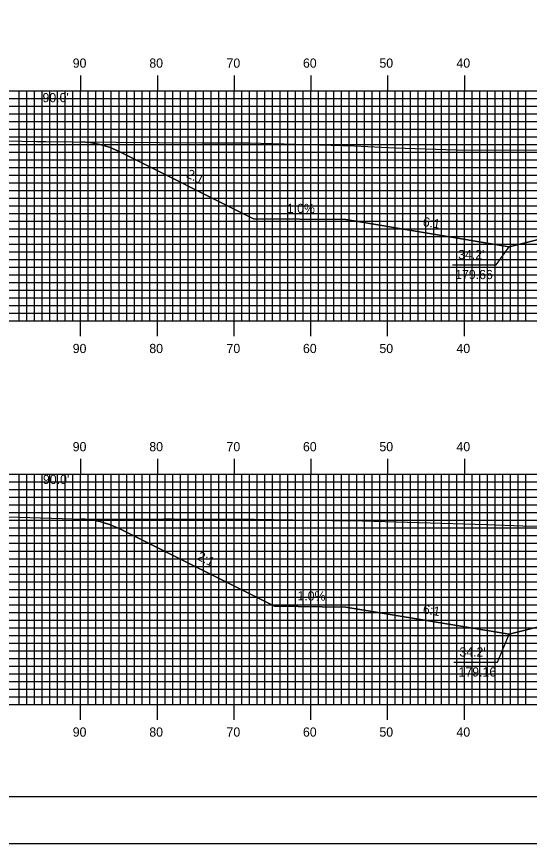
# Model space of a CAD drawing. Extents: x 1797207 to 1797550, y 442591 to 442811.
# Drawn here: x 1797274.6 to 1797341.4, y 442590.5 to 442698.3 of the extents above; entities that cross this region are included whole.
import ezdxf

# ---------------------------------------------------------------- set-up
doc = ezdxf.new("R2010")
doc.units = 0
for name, color, linetype in [('ANNOTATION', 7, 'Continuous'), ('BORDER', 7, 'Continuous'), ('D_Roadway_Centerline', 7, 'Continuous'), ('D_Roadway_SlopeLines', 7, 'Continuous'), ('D_Text_Standard', 7, 'Continuous'), ('H_V ANNOTATION', 7, 'Continuous'), ('MAJOR', 7, 'Continuous'), ('MINOR', 7, 'Continuous'), ('PLOT BOUNDARY', 7, 'Continuous'), ('S_Roadway_Centerline', 7, 'Continuous')]:
    doc.layers.add(name, color=color, linetype=linetype)

msp = doc.modelspace()

# ---------------------------------------------------------------- linework, layer by layer
at = {"layer": 'ANNOTATION'}
for points in [[(1797331.39, 442665.98), (1797337.08, 442665.98), (1797338.76, 442668.33)], [(1797331.54, 442614.18), (1797337.24, 442614.18), (1797338.76, 442617.83)]]:
    msp.add_lwpolyline(points, dxfattribs=at)
at = {"layer": 'BORDER'}
msp.add_lwpolyline([(1797223.33, 442596.67), (1797543.33, 442596.67), (1797543.33, 442806.67), (1797223.33, 442806.67)], close=True, dxfattribs=at)
at = {"layer": 'D_Roadway_Centerline'}
for points in [[(1797282.93, 442682.01), (1797284.18, 442681.93), (1797285.43, 442681.68), (1797286.68, 442681.29), (1797287.93, 442680.74), (1797305.44, 442671.99), (1797317.5, 442671.87), (1797338.76, 442668.33), (1797342.76, 442669.33), (1797352.93, 442671.87), (1797360.93, 442672.19), (1797372.93, 442671.95), (1797384.93, 442671.71), (1797392.93, 442671.39), (1797403.11, 442668.85), (1797407.11, 442667.85), (1797428.37, 442671.39), (1797448.91, 442671.59), (1797457.93, 442676.11), (1797459.18, 442676.65), (1797460.43, 442677.04), (1797461.68, 442677.28), (1797462.93, 442677.35)], [(1797282.93, 442632.85), (1797284.18, 442632.77), (1797285.43, 442632.53), (1797286.68, 442632.14), (1797287.93, 442631.59), (1797308.19, 442621.46), (1797317.5, 442621.37), (1797338.76, 442617.83), (1797342.76, 442618.83), (1797352.93, 442621.37), (1797360.93, 442621.69), (1797372.93, 442621.45), (1797384.93, 442621.21), (1797392.93, 442620.89), (1797403.11, 442618.35), (1797407.11, 442617.35), (1797428.37, 442620.89), (1797445.43, 442621.06), (1797457.93, 442627.31), (1797459.18, 442627.85), (1797460.43, 442628.22), (1797461.68, 442628.41), (1797462.93, 442628.43)]]:
    msp.add_lwpolyline(points, dxfattribs=at)
at = {"layer": 'D_Roadway_SlopeLines'}
for points in [[(1797317.5, 442671.87), (1797305.44, 442671.99), (1797287.93, 442680.74), (1797286.68, 442681.29), (1797285.43, 442681.68), (1797284.18, 442681.93), (1797282.93, 442682.01)], [(1797338.76, 442668.33), (1797317.5, 442671.87)], [(1797352.93, 442671.87), (1797338.76, 442668.33)], [(1797317.5, 442621.37), (1797308.19, 442621.46), (1797287.93, 442631.59), (1797286.68, 442632.14), (1797285.43, 442632.53), (1797284.18, 442632.77), (1797282.93, 442632.85)], [(1797338.76, 442617.83), (1797317.5, 442621.37)], [(1797352.93, 442621.37), (1797338.76, 442617.83)]]:
    msp.add_lwpolyline(points, dxfattribs=at)
at = {"layer": 'MAJOR'}
for p, q in [((1797282.93, 442690.67), (1797282.93, 442688.67)), ((1797292.93, 442690.67), (1797292.93, 442688.67)), ((1797302.93, 442690.67), (1797302.93, 442688.67)), ((1797312.93, 442690.67), (1797312.93, 442688.67)), ((1797322.93, 442690.67), (1797322.93, 442688.67)), ((1797332.93, 442690.67), (1797332.93, 442688.67)), ((1797232.93, 442688.67), (1797512.93, 442688.67)), ((1797232.93, 442688.67), (1797512.93, 442688.67)), ((1797282.93, 442658.67), (1797282.93, 442688.67)), ((1797292.93, 442658.67), (1797292.93, 442688.67)), ((1797302.93, 442658.67), (1797302.93, 442688.67)), ((1797312.93, 442658.67), (1797312.93, 442688.67)), ((1797322.93, 442658.67), (1797322.93, 442688.67)), ((1797332.93, 442658.67), (1797332.93, 442688.67)), ((1797232.93, 442683.67), (1797512.93, 442683.67)), ((1797232.93, 442678.67), (1797512.93, 442678.67)), ((1797232.93, 442673.67), (1797512.93, 442673.67)), ((1797232.93, 442668.67), (1797512.93, 442668.67)), ((1797232.93, 442663.67), (1797512.93, 442663.67)), ((1797232.93, 442658.67), (1797512.93, 442658.67)), ((1797232.93, 442658.67), (1797512.93, 442658.67)), ((1797282.93, 442656.66), (1797282.93, 442658.67)), ((1797292.93, 442656.66), (1797292.93, 442658.67)), ((1797302.93, 442656.66), (1797302.93, 442658.67)), ((1797312.93, 442656.66), (1797312.93, 442658.67)), ((1797322.93, 442656.66), (1797322.93, 442658.67)), ((1797332.93, 442656.66), (1797332.93, 442658.67)), ((1797282.93, 442640.67), (1797282.93, 442638.67)), ((1797292.93, 442640.67), (1797292.93, 442638.67)), ((1797302.93, 442640.67), (1797302.93, 442638.67)), ((1797312.93, 442640.67), (1797312.93, 442638.67)), ((1797322.93, 442640.67), (1797322.93, 442638.67)), ((1797332.93, 442640.67), (1797332.93, 442638.67)), ((1797232.93, 442638.67), (1797512.93, 442638.67)), ((1797232.93, 442638.67), (1797512.93, 442638.67)), ((1797282.93, 442608.67), (1797282.93, 442638.67)), ((1797292.93, 442608.67), (1797292.93, 442638.67)), ((1797302.93, 442608.67), (1797302.93, 442638.67)), ((1797312.93, 442608.67), (1797312.93, 442638.67)), ((1797322.93, 442608.67), (1797322.93, 442638.67)), ((1797332.93, 442608.67), (1797332.93, 442638.67)), ((1797232.93, 442633.67), (1797512.93, 442633.67)), ((1797232.93, 442628.67), (1797512.93, 442628.67)), ((1797232.93, 442623.67), (1797512.93, 442623.67)), ((1797232.93, 442618.67), (1797512.93, 442618.67)), ((1797232.93, 442613.67), (1797512.93, 442613.67)), ((1797232.93, 442608.67), (1797512.93, 442608.67)), ((1797232.93, 442608.67), (1797512.93, 442608.67)), ((1797282.93, 442606.66), (1797282.93, 442608.67)), ((1797292.93, 442606.66), (1797292.93, 442608.67)), ((1797302.93, 442606.66), (1797302.93, 442608.67)), ((1797312.93, 442606.66), (1797312.93, 442608.67)), ((1797322.93, 442606.66), (1797322.93, 442608.67)), ((1797332.93, 442606.66), (1797332.93, 442608.67))]:
    msp.add_line(p, q, dxfattribs=at)
at = {"layer": 'MINOR'}
for p, q in [((1797274.93, 442658.67), (1797274.93, 442688.67)), ((1797275.93, 442658.67), (1797275.93, 442688.67)), ((1797276.93, 442658.67), (1797276.93, 442688.67)), ((1797277.93, 442658.67), (1797277.93, 442688.67)), ((1797278.93, 442658.67), (1797278.93, 442688.67)), ((1797279.93, 442658.67), (1797279.93, 442688.67)), ((1797280.93, 442658.67), (1797280.93, 442688.67)), ((1797281.93, 442658.67), (1797281.93, 442688.67)), ((1797283.93, 442658.67), (1797283.93, 442688.67)), ((1797284.93, 442658.67), (1797284.93, 442688.67)), ((1797285.93, 442658.67), (1797285.93, 442688.67)), ((1797286.93, 442658.67), (1797286.93, 442688.67)), ((1797287.93, 442658.67), (1797287.93, 442688.67)), ((1797288.93, 442658.67), (1797288.93, 442688.67)), ((1797289.93, 442658.67), (1797289.93, 442688.67)), ((1797290.93, 442658.67), (1797290.93, 442688.67)), ((1797291.93, 442658.67), (1797291.93, 442688.67)), ((1797293.93, 442658.67), (1797293.93, 442688.67)), ((1797294.93, 442658.67), (1797294.93, 442688.67)), ((1797295.93, 442658.67), (1797295.93, 442688.67)), ((1797296.93, 442658.67), (1797296.93, 442688.67)), ((1797297.93, 442658.67), (1797297.93, 442688.67)), ((1797298.93, 442658.67), (1797298.93, 442688.67)), ((1797299.93, 442658.67), (1797299.93, 442688.67)), ((1797300.93, 442658.67), (1797300.93, 442688.67)), ((1797301.93, 442658.67), (1797301.93, 442688.67)), ((1797303.93, 442658.67), (1797303.93, 442688.67)), ((1797304.93, 442658.67), (1797304.93, 442688.67)), ((1797305.93, 442658.67), (1797305.93, 442688.67)), ((1797306.93, 442658.67), (1797306.93, 442688.67)), ((1797307.93, 442658.67), (1797307.93, 442688.67)), ((1797308.93, 442658.67), (1797308.93, 442688.67)), ((1797309.93, 442658.67), (1797309.93, 442688.67)), ((1797310.93, 442658.67), (1797310.93, 442688.67)), ((1797311.93, 442658.67), (1797311.93, 442688.67)), ((1797313.93, 442658.67), (1797313.93, 442688.67)), ((1797314.93, 442658.67), (1797314.93, 442688.67)), ((1797315.93, 442658.67), (1797315.93, 442688.67)), ((1797316.93, 442658.67), (1797316.93, 442688.67)), ((1797317.93, 442658.67), (1797317.93, 442688.67)), ((1797318.93, 442658.67), (1797318.93, 442688.67)), ((1797319.93, 442658.67), (1797319.93, 442688.67)), ((1797320.93, 442658.67), (1797320.93, 442688.67)), ((1797321.93, 442658.67), (1797321.93, 442688.67)), ((1797323.93, 442658.67), (1797323.93, 442688.67)), ((1797324.93, 442658.67), (1797324.93, 442688.67)), ((1797325.93, 442658.67), (1797325.93, 442688.67)), ((1797326.93, 442658.67), (1797326.93, 442688.67)), ((1797327.93, 442658.67), (1797327.93, 442688.67)), ((1797328.93, 442658.67), (1797328.93, 442688.67)), ((1797329.93, 442658.67), (1797329.93, 442688.67)), ((1797330.93, 442658.67), (1797330.93, 442688.67)), ((1797331.93, 442658.67), (1797331.93, 442688.67)), ((1797333.93, 442658.67), (1797333.93, 442688.67)), ((1797334.93, 442658.67), (1797334.93, 442688.67)), ((1797335.93, 442658.67), (1797335.93, 442688.67)), ((1797336.93, 442658.67), (1797336.93, 442688.67)), ((1797337.93, 442658.67), (1797337.93, 442688.67)), ((1797338.93, 442658.67), (1797338.93, 442688.67)), ((1797339.93, 442658.67), (1797339.93, 442688.67)), ((1797340.93, 442658.67), (1797340.93, 442688.67)), ((1797232.93, 442687.67), (1797512.93, 442687.67)), ((1797232.93, 442686.67), (1797512.93, 442686.67)), ((1797232.93, 442685.67), (1797512.93, 442685.67)), ((1797232.93, 442684.67), (1797512.93, 442684.67)), ((1797232.93, 442682.67), (1797512.93, 442682.67)), ((1797232.93, 442681.67), (1797512.93, 442681.67)), ((1797232.93, 442680.67), (1797512.93, 442680.67)), ((1797232.93, 442679.67), (1797512.93, 442679.67)), ((1797232.93, 442677.67), (1797512.93, 442677.67)), ((1797232.93, 442676.67), (1797512.93, 442676.67)), ((1797232.93, 442675.67), (1797512.93, 442675.67)), ((1797232.93, 442674.67), (1797512.93, 442674.67)), ((1797232.93, 442672.67), (1797512.93, 442672.67)), ((1797232.93, 442671.67), (1797512.93, 442671.67)), ((1797232.93, 442670.67), (1797512.93, 442670.67)), ((1797232.93, 442669.67), (1797512.93, 442669.67)), ((1797232.93, 442667.67), (1797512.93, 442667.67)), ((1797232.93, 442666.67), (1797512.93, 442666.67)), ((1797232.93, 442665.67), (1797512.93, 442665.67)), ((1797232.93, 442664.67), (1797512.93, 442664.67)), ((1797232.93, 442662.67), (1797512.93, 442662.67)), ((1797232.93, 442661.67), (1797512.93, 442661.67)), ((1797232.93, 442660.67), (1797512.93, 442660.67)), ((1797232.93, 442659.67), (1797512.93, 442659.67)), ((1797274.93, 442608.67), (1797274.93, 442638.67)), ((1797275.93, 442608.67), (1797275.93, 442638.67)), ((1797276.93, 442608.67), (1797276.93, 442638.67)), ((1797277.93, 442608.67), (1797277.93, 442638.67)), ((1797278.93, 442608.67), (1797278.93, 442638.67)), ((1797279.93, 442608.67), (1797279.93, 442638.67)), ((1797280.93, 442608.67), (1797280.93, 442638.67)), ((1797281.93, 442608.67), (1797281.93, 442638.67)), ((1797283.93, 442608.67), (1797283.93, 442638.67)), ((1797284.93, 442608.67), (1797284.93, 442638.67)), ((1797285.93, 442608.67), (1797285.93, 442638.67)), ((1797286.93, 442608.67), (1797286.93, 442638.67)), ((1797287.93, 442608.67), (1797287.93, 442638.67)), ((1797288.93, 442608.67), (1797288.93, 442638.67)), ((1797289.93, 442608.67), (1797289.93, 442638.67)), ((1797290.93, 442608.67), (1797290.93, 442638.67)), ((1797291.93, 442608.67), (1797291.93, 442638.67)), ((1797293.93, 442608.67), (1797293.93, 442638.67)), ((1797294.93, 442608.67), (1797294.93, 442638.67)), ((1797295.93, 442608.67), (1797295.93, 442638.67)), ((1797296.93, 442608.67), (1797296.93, 442638.67)), ((1797297.93, 442608.67), (1797297.93, 442638.67)), ((1797298.93, 442608.67), (1797298.93, 442638.67)), ((1797299.93, 442608.67), (1797299.93, 442638.67)), ((1797300.93, 442608.67), (1797300.93, 442638.67)), ((1797301.93, 442608.67), (1797301.93, 442638.67)), ((1797303.93, 442608.67), (1797303.93, 442638.67)), ((1797304.93, 442608.67), (1797304.93, 442638.67)), ((1797305.93, 442608.67), (1797305.93, 442638.67)), ((1797306.93, 442608.67), (1797306.93, 442638.67)), ((1797307.93, 442608.67), (1797307.93, 442638.67)), ((1797308.93, 442608.67), (1797308.93, 442638.67)), ((1797309.93, 442608.67), (1797309.93, 442638.67)), ((1797310.93, 442608.67), (1797310.93, 442638.67)), ((1797311.93, 442608.67), (1797311.93, 442638.67)), ((1797313.93, 442608.67), (1797313.93, 442638.67)), ((1797314.93, 442608.67), (1797314.93, 442638.67)), ((1797315.93, 442608.67), (1797315.93, 442638.67)), ((1797316.93, 442608.67), (1797316.93, 442638.67)), ((1797317.93, 442608.67), (1797317.93, 442638.67)), ((1797318.93, 442608.67), (1797318.93, 442638.67)), ((1797319.93, 442608.67), (1797319.93, 442638.67)), ((1797320.93, 442608.67), (1797320.93, 442638.67)), ((1797321.93, 442608.67), (1797321.93, 442638.67)), ((1797323.93, 442608.67), (1797323.93, 442638.67)), ((1797324.93, 442608.67), (1797324.93, 442638.67)), ((1797325.93, 442608.67), (1797325.93, 442638.67)), ((1797326.93, 442608.67), (1797326.93, 442638.67)), ((1797327.93, 442608.67), (1797327.93, 442638.67)), ((1797328.93, 442608.67), (1797328.93, 442638.67)), ((1797329.93, 442608.67), (1797329.93, 442638.67)), ((1797330.93, 442608.67), (1797330.93, 442638.67)), ((1797331.93, 442608.67), (1797331.93, 442638.67)), ((1797333.93, 442608.67), (1797333.93, 442638.67)), ((1797334.93, 442608.67), (1797334.93, 442638.67)), ((1797335.93, 442608.67), (1797335.93, 442638.67)), ((1797336.93, 442608.67), (1797336.93, 442638.67)), ((1797337.93, 442608.67), (1797337.93, 442638.67)), ((1797338.93, 442608.67), (1797338.93, 442638.67)), ((1797339.93, 442608.67), (1797339.93, 442638.67)), ((1797340.93, 442608.67), (1797340.93, 442638.67)), ((1797232.93, 442637.67), (1797512.93, 442637.67)), ((1797232.93, 442636.67), (1797512.93, 442636.67)), ((1797232.93, 442635.67), (1797512.93, 442635.67)), ((1797232.93, 442634.67), (1797512.93, 442634.67)), ((1797232.93, 442632.67), (1797512.93, 442632.67)), ((1797232.93, 442631.67), (1797512.93, 442631.67)), ((1797232.93, 442630.67), (1797512.93, 442630.67)), ((1797232.93, 442629.67), (1797512.93, 442629.67)), ((1797232.93, 442627.67), (1797512.93, 442627.67)), ((1797232.93, 442626.67), (1797512.93, 442626.67)), ((1797232.93, 442625.67), (1797512.93, 442625.67)), ((1797232.93, 442624.67), (1797512.93, 442624.67)), ((1797232.93, 442622.67), (1797512.93, 442622.67)), ((1797232.93, 442621.67), (1797512.93, 442621.67)), ((1797232.93, 442620.67), (1797512.93, 442620.67)), ((1797232.93, 442619.67), (1797512.93, 442619.67)), ((1797232.93, 442617.67), (1797512.93, 442617.67)), ((1797232.93, 442616.67), (1797512.93, 442616.67)), ((1797232.93, 442615.67), (1797512.93, 442615.67)), ((1797232.93, 442614.67), (1797512.93, 442614.67)), ((1797232.93, 442612.67), (1797512.93, 442612.67)), ((1797232.93, 442611.67), (1797512.93, 442611.67)), ((1797232.93, 442610.67), (1797512.93, 442610.67)), ((1797232.93, 442609.67), (1797512.93, 442609.67))]:
    msp.add_line(p, q, dxfattribs=at)
at = {"layer": 'PLOT BOUNDARY'}
msp.add_lwpolyline([(1797207.14, 442590.55), (1797547.14, 442590.55), (1797547.14, 442810.55), (1797207.14, 442810.55)], close=True, dxfattribs=at)
at = {"layer": 'S_Roadway_Centerline'}
for points in [[(1797232.93, 442682.78), (1797237.14, 442682.75), (1797249.82, 442682.58), (1797257.81, 442682.5), (1797277.16, 442682.06), (1797278.41, 442682.05), (1797281.96, 442682.02), (1797298.75, 442681.88), (1797304.88, 442681.87), (1797318.6, 442681.48), (1797323.86, 442681.23), (1797331.88, 442680.97), (1797354, 442680.91)], [(1797232.93, 442633.32), (1797234.1, 442633.3), (1797236.32, 442633.26), (1797254.57, 442633.26), (1797263.43, 442633.34), (1797270.41, 442633.18), (1797274.92, 442633.08), (1797281.92, 442632.85), (1797291.92, 442632.83), (1797293.77, 442632.85), (1797295.12, 442632.87), (1797305.54, 442632.83), (1797315.71, 442632.64), (1797319.65, 442632.6), (1797335.82, 442632.12), (1797340.53, 442631.94), (1797346.87, 442631.81)]]:
    msp.add_lwpolyline(points, dxfattribs=at)

# ---------------------------------------------------------------- texts
at = {"layer": 'ANNOTATION'}
for s, rotation, p in [('2:1', 333.4349, (1797296.62, 442677.43)), ('1.0%', 359.4271, (1797309.8, 442672.75)), ('6:1', 350.5377, (1797327.46, 442671.04)), ('2:1', 333.4349, (1797298, 442627.6)), ('1.0%', 359.4271, (1797311.17, 442622.23)), ('6:1', 350.5375, (1797327.46, 442620.54))]:
    msp.add_text(s, height=1.2, rotation=rotation, dxfattribs=at).set_placement(p)
for s, p in [("34.2'", (1797332.12, 442666.71)), ('179.66', (1797331.73, 442664.11)), ("34.2'", (1797332.28, 442614.91)), ('179.16', (1797332.17, 442612.31))]:
    msp.add_text(s, height=1.2, dxfattribs=at).set_placement(p)
at = {"layer": 'D_Text_Standard'}
for p in [(1797277.96, 442687.17), (1797278.02, 442637.4)]:
    msp.add_text("90.0'", height=1.2, dxfattribs=at).set_placement(p)
at = {"layer": 'H_V ANNOTATION'}
for s, p in [('90', (1797281.9, 442691.67)), ('80', (1797291.88, 442691.67)), ('70', (1797301.94, 442691.67)), ('60', (1797311.9, 442691.67)), ('50', (1797321.86, 442691.67)), ('40', (1797331.9, 442691.67)), ('90', (1797281.9, 442654.47)), ('80', (1797291.88, 442654.47)), ('70', (1797301.94, 442654.47)), ('60', (1797311.9, 442654.47)), ('50', (1797321.86, 442654.47)), ('40', (1797331.9, 442654.47)), ('90', (1797281.9, 442641.67)), ('80', (1797291.88, 442641.67)), ('70', (1797301.94, 442641.67)), ('60', (1797311.9, 442641.67)), ('50', (1797321.86, 442641.67)), ('40', (1797331.9, 442641.67)), ('90', (1797281.9, 442604.47)), ('80', (1797291.88, 442604.47)), ('70', (1797301.94, 442604.47)), ('60', (1797311.9, 442604.47)), ('50', (1797321.86, 442604.47)), ('40', (1797331.9, 442604.47))]:
    msp.add_text(s, height=1.2, dxfattribs=at).set_placement(p)

doc.saveas('drawing.dxf')
